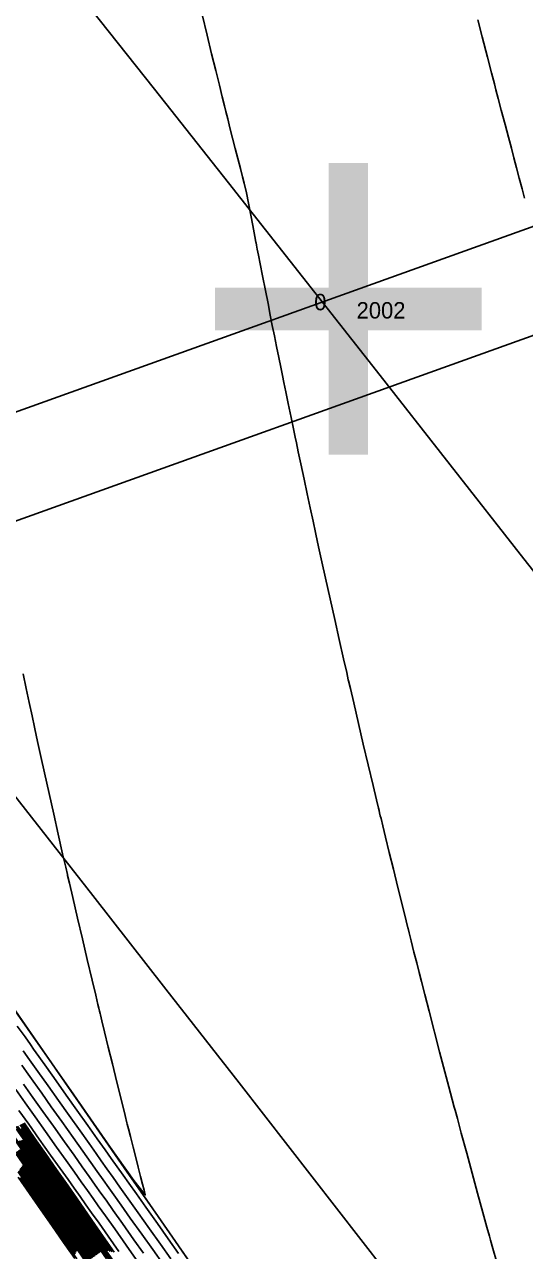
# Model space of a CAD drawing. Extents: x 74655 to 77873, y 48844 to 50507.
# Drawn here: x 75126.62 to 75130.27, y 49766.3 to 49775.27 of the extents above; entities that cross this region are included whole.
import ezdxf

# ---------------------------------------------------------------- set-up
doc = ezdxf.new("R2010")
doc.units = 0
for name, color, linetype in [('2', 7, 'Continuous'), ('24', 7, 'Continuous'), ('50', 7, 'Continuous'), ('62', 7, 'Continuous'), ('7', 7, 'Continuous')]:
    doc.layers.add(name, color=color, linetype=linetype)

msp = doc.modelspace()

# ---------------------------------------------------------------- linework, layer by layer
at = {"layer": '2'}
for radius in [833.5111, 829.5111, 818.5111, 807.5111, 803.5111]:
    msp.add_arc((74494.001, 49274.1292), radius, 30.8050451, 46.6978585, dxfattribs=at)
at = {"layer": '50'}
for points in [[(75127.9143, 49775.3434), (75127.9509, 49775.193), (75127.9843, 49775.0567), (75128.0143, 49774.9346), (75128.0411, 49774.8267), (75128.0624, 49774.7408), (75128.0783, 49774.6767), (75128.0888, 49774.6345), (75128.1023, 49774.5809), (75128.1186, 49774.5159), (75128.1379, 49774.4395), (75128.1569, 49774.3641), (75128.1757, 49774.2898), (75128.1943, 49774.2166), (75128.2096, 49774.1564), (75128.2217, 49774.1091), (75128.2394, 49774.0404)], [(75129.9314, 49775.3053), (75129.9632, 49775.1814), (75130.0016, 49775.0321), (75130.0311, 49774.9177), (75130.0517, 49774.838), (75130.0634, 49774.7931), (75130.0803, 49774.7285), (75130.1024, 49774.6442), (75130.1297, 49774.5403), (75130.1541, 49774.4474), (75130.1758, 49774.3655), (75130.1945, 49774.2947), (75130.214, 49774.2216), (75130.2341, 49774.1462), (75130.2549, 49774.0686), (75130.2731, 49774.0005)], [(75129.6515, 49767.7536), (75129.5743, 49768.0519), (75129.5429, 49768.1734), (75129.5187, 49768.2673), (75129.5018, 49768.3336), (75129.4836, 49768.4056), (75129.4639, 49768.4832), (75129.4429, 49768.5665), (75129.4284, 49768.624), (75129.4205, 49768.6556), (75129.419, 49768.6615), (75129.4061, 49768.7135), (75129.3818, 49768.8116), (75129.346, 49768.9558), (75129.313, 49769.0896), (75129.2828, 49769.2129), (75129.2554, 49769.3258), (75129.2353, 49769.4082), (75129.2227, 49769.4602), (75129.2175, 49769.4818), (75129.2128, 49769.5015), (75129.2084, 49769.5195), (75129.2046, 49769.5356), (75129.19, 49769.5967), (75129.1649, 49769.7027), (75129.129, 49769.8538), (75129.0934, 49770.005), (75129.058, 49770.1563), (75129.0229, 49770.3079), (75128.9988, 49770.4117), (75128.9858, 49770.4679), (75128.9838, 49770.4765), (75128.9717, 49770.53), (75128.9494, 49770.6285), (75128.9169, 49770.7719), (75128.884, 49770.9184), (75128.8506, 49771.0679), (75128.8169, 49771.2203), (75128.7903, 49771.3404), (75128.771, 49771.4282), (75128.759, 49771.4836), (75128.7439, 49771.553), (75128.7259, 49771.6365), (75128.7049, 49771.7341), (75128.683, 49771.8366), (75128.6601, 49771.944), (75128.6363, 49772.0563), (75128.6176, 49772.1449), (75128.6039, 49772.2098), (75128.5954, 49772.2509), (75128.5825, 49772.3126), (75128.5655, 49772.3949), (75128.5442, 49772.4977), (75128.5266, 49772.5833), (75128.5125, 49772.6517), (75128.5021, 49772.7027), (75128.4897, 49772.7636), (75128.4754, 49772.8345), (75128.4591, 49772.9152), (75128.4433, 49772.9936), (75128.4281, 49773.0696), (75128.4134, 49773.1432), (75128.3965, 49773.2284), (75128.3775, 49773.3251), (75128.3562, 49773.4332), (75128.3393, 49773.5196), (75128.3266, 49773.5843), (75128.3183, 49773.6273), (75128.3125, 49773.6572), (75128.3092, 49773.674), (75128.3085, 49773.6778), (75128.3004, 49773.7202), (75128.285, 49773.8012), (75128.2394, 49774.0404)], [(75122.5232, 49773.8581), (75123.1719, 49772.9229), (75123.5385, 49772.3944), (75123.9474, 49771.8049), (75124.3985, 49771.1544), (75124.8235, 49770.5418), (75125.2223, 49769.9668), (75125.5949, 49769.4296), (75126.0081, 49768.834), (75126.4618, 49768.1799), (75126.956, 49767.4673), (75127.313, 49766.9527), (75127.5327, 49766.636), (75127.6974, 49766.3984)], [(75126.6058, 49770.5193), (75126.6287, 49770.4119), (75126.6506, 49770.3094), (75126.6716, 49770.2118), (75126.6896, 49770.1283), (75126.7047, 49770.0589), (75126.7167, 49770.0035), (75126.736, 49769.9157), (75126.7626, 49769.7956), (75126.7963, 49769.6431), (75126.8297, 49769.4937), (75126.8626, 49769.3472), (75126.8951, 49769.2037), (75126.9174, 49769.1052), (75126.9295, 49769.0517), (75126.9315, 49769.0432), (75126.9445, 49768.987), (75126.9686, 49768.8831), (75127.0037, 49768.7316), (75127.0391, 49768.5803), (75127.0747, 49768.4291), (75127.1105, 49768.278), (75127.1366, 49768.1684), (75127.1529, 49768.1001), (75127.1593, 49768.0731), (75127.1645, 49768.0516), (75127.1684, 49768.0354), (75127.171, 49768.0247), (75127.1819, 49767.9799), (75127.201, 49767.9011), (75127.2285, 49767.7882), (75127.2587, 49767.6649), (75127.2917, 49767.5311), (75127.3275, 49767.3868), (75127.3521, 49767.2876), (75127.3655, 49767.2334), (75127.3679, 49767.2241), (75127.3761, 49767.1913), (75127.3903, 49767.135), (75127.4105, 49767.0551), (75127.4295, 49766.9798), (75127.4475, 49766.9089), (75127.4644, 49766.8426), (75127.4787, 49766.7867), (75127.4904, 49766.7414), (75127.4994, 49766.7065), (75127.4166, 49766.8113), (75127.242, 49767.0557), (75126.9756, 49767.4397), (75126.6607, 49767.8937), (75126.2974, 49768.4176)], [(75125.6878, 49769.2951), (75126.2036, 49768.5515), (75126.4853, 49768.1452), (75126.791, 49767.7046), (75127.1205, 49767.2296), (75127.3676, 49766.8733), (75127.5323, 49766.6357), (75127.6971, 49766.3982)], [(75127.7432, 49766.2785), (75127.6673, 49766.3856), (75127.5876, 49766.4982), (75127.504, 49766.6161), (75127.4345, 49766.7142), (75127.379, 49766.7925), (75127.3375, 49766.851), (75127.2947, 49766.9113), (75127.2506, 49766.9735), (75127.2052, 49767.0375), (75127.1482, 49767.118), (75127.0795, 49767.2148), (75126.9991, 49767.3281), (75126.9218, 49767.4371), (75126.8476, 49767.5417), (75126.7765, 49767.6419), (75126.7215, 49767.7194), (75126.6825, 49767.7743), (75126.6596, 49767.8066), (75126.6199, 49767.8625), (75126.5634, 49767.9421)], [(75127.6862, 49766.2389), (75127.6102, 49766.346), (75127.5305, 49766.4586), (75127.4469, 49766.5765), (75127.3747, 49766.6784), (75127.3138, 49766.7642), (75127.2644, 49766.834), (75127.2189, 49766.8981), (75127.1775, 49766.9565), (75127.1401, 49767.0092), (75127.0884, 49767.0821), (75127.0224, 49767.1752), (75126.942, 49767.2885), (75126.8639, 49767.3986), (75126.7881, 49767.5055), (75126.7145, 49767.6092), (75126.6538, 49767.6947), (75126.606, 49767.7621)], [(75129.6515, 49767.7536), (75129.7192, 49767.4972), (75129.7435, 49767.4049), (75129.7585, 49767.3485), (75129.7639, 49767.3281), (75129.7809, 49767.2651), (75129.8093, 49767.1595), (75129.8493, 49767.0114), (75129.8891, 49766.8649), (75129.9286, 49766.7203), (75129.968, 49766.5773), (75129.997, 49766.4721), (75130.0156, 49766.4048), (75130.0239, 49766.3751), (75130.0408, 49766.3146), (75130.0665, 49766.2232)], [(75126.5955, 49767.657), (75126.6303, 49767.6078), (75126.6791, 49767.5391), (75126.7418, 49767.4507), (75126.8115, 49767.3524), (75126.8882, 49767.2444), (75126.9718, 49767.1265), (75127.0431, 49767.026), (75127.1019, 49766.943), (75127.1484, 49766.8774), (75127.1918, 49766.8162), (75127.2321, 49766.7595), (75127.2691, 49766.7072), (75127.3217, 49766.633), (75127.3898, 49766.5369), (75127.4734, 49766.419), (75127.5532, 49766.3065), (75127.6291, 49766.1993)], [(75127.4331, 49766.2355), (75127.3592, 49766.3398), (75127.2757, 49766.4577), (75127.2076, 49766.5538), (75127.155, 49766.628), (75127.1179, 49766.6803), (75127.0766, 49766.7386), (75127.031, 49766.8028), (75126.9812, 49766.873), (75126.9213, 49766.9575), (75126.8511, 49767.0565), (75126.7708, 49767.1698), (75126.6941, 49767.2779), (75126.621, 49767.3809), (75126.5516, 49767.4787)], [(75127.4861, 49766.2809), (75127.4163, 49766.3794), (75127.3327, 49766.4973), (75127.2647, 49766.5934), (75127.2121, 49766.6676), (75127.175, 49766.7199), (75127.1336, 49766.7782), (75127.0881, 49766.8424), (75127.0383, 49766.9126), (75126.9784, 49766.9971), (75126.9082, 49767.0961), (75126.8278, 49767.2094), (75126.7511, 49767.3175), (75126.6781, 49767.4205), (75126.6087, 49767.5183)], [(75126.5757, 49767.3247), (75126.6469, 49767.2243), (75126.7241, 49767.1155), (75126.8071, 49766.9984), (75126.8773, 49766.8994), (75126.9347, 49766.8185), (75126.9792, 49766.7558), (75127.0228, 49766.6944), (75127.0654, 49766.6343), (75127.107, 49766.5755), (75127.1611, 49766.4992), (75127.2277, 49766.4052), (75127.3067, 49766.2938)], [(75127.239, 49766.2249), (75127.1349, 49766.3745), (75127.0247, 49766.5329), (75126.932, 49766.6661), (75126.8568, 49766.7742), (75126.7991, 49766.8571), (75126.7409, 49766.9408), (75126.6822, 49767.0251), (75126.623, 49767.1102), (75126.556, 49767.2065)], [(75127.2555, 49766.2197), (75127.1515, 49766.3691), (75127.0399, 49766.5295), (75126.9467, 49766.6634), (75126.8719, 49766.771), (75126.8154, 49766.8521), (75126.7571, 49766.9359), (75126.6968, 49767.0226), (75126.6346, 49767.1119), (75126.5657, 49767.211)], [(75127.2277, 49766.2965), (75127.1564, 49766.399), (75127.0766, 49766.5137), (75126.9881, 49766.6408), (75126.8912, 49766.7801), (75126.8038, 49766.9057), (75126.7261, 49767.0174), (75126.6579, 49767.1154), (75126.585, 49767.2202)], [(75127.2426, 49766.2936), (75127.1682, 49766.4005), (75127.0872, 49766.5168), (75126.9998, 49766.6425), (75126.9058, 49766.7776), (75126.8194, 49766.9017), (75126.7407, 49767.0149), (75126.6696, 49767.1171), (75126.5946, 49767.2248)], [(75127.2575, 49766.2906), (75127.1799, 49766.4021), (75127.0979, 49766.5199), (75127.0114, 49766.6442), (75126.9204, 49766.775), (75126.835, 49766.8977), (75126.7553, 49767.0123), (75126.6812, 49767.1188), (75126.6043, 49767.2293)], [(75127.2723, 49766.2877), (75127.1917, 49766.4036), (75127.1086, 49766.523), (75127.0231, 49766.646), (75126.935, 49766.7725), (75126.8507, 49766.8937), (75126.7699, 49767.0097), (75126.6928, 49767.1205), (75126.6139, 49767.2339)], [(75127.1357, 49766.2628), (75127.0165, 49766.4341), (75126.908, 49766.59), (75126.8101, 49766.7306), (75126.7229, 49766.8559), (75126.6235, 49766.9987), (75126.5119, 49767.1591)], [(75127.1443, 49766.2688), (75127.0251, 49766.4401), (75126.9176, 49766.5946), (75126.8218, 49766.7323), (75126.7376, 49766.8533), (75126.6392, 49766.9947), (75126.5265, 49767.1566)], [(75127.2156, 49766.2402), (75127.133, 49766.3588), (75127.0494, 49766.479), (75126.9647, 49766.6007), (75126.8789, 49766.724), (75126.7953, 49766.8442), (75126.7138, 49766.9612), (75126.6345, 49767.0753), (75126.5541, 49767.1908)], [(75126.5917, 49767.192), (75126.6637, 49767.0886), (75126.7462, 49766.97), (75126.8288, 49766.8514), (75126.9113, 49766.7327), (75126.9939, 49766.6141), (75127.0806, 49766.4896), (75127.1713, 49766.3591), (75127.2662, 49766.2228)], [(75127.1097, 49766.2448), (75126.9905, 49766.4161), (75126.8947, 49766.5538), (75126.8222, 49766.658), (75126.773, 49766.7286), (75126.7138, 49766.8137), (75126.6445, 49766.9132), (75126.5652, 49767.0272)], [(75127.1183, 49766.2508), (75126.9992, 49766.4221), (75126.9033, 49766.5598), (75126.8308, 49766.664), (75126.7817, 49766.7346), (75126.7225, 49766.8197), (75126.6532, 49766.9192), (75126.5739, 49767.0332)], [(75127.153, 49766.2748), (75127.0338, 49766.4461), (75126.9273, 49766.5992), (75126.8334, 49766.7341), (75126.7522, 49766.8508), (75126.6823, 49766.9512), (75126.6237, 49767.0354), (75126.5764, 49767.1033)], [(75127.127, 49766.2568), (75127.0078, 49766.4281), (75126.912, 49766.5658), (75126.8395, 49766.67), (75126.7903, 49766.7406), (75126.7311, 49766.8257), (75126.6619, 49766.9252), (75126.5825, 49767.0392)], [(75127.1616, 49766.2808), (75127.0424, 49766.4521), (75126.9369, 49766.6037), (75126.845, 49766.7358), (75126.7668, 49766.8482), (75126.6979, 49766.9472), (75126.6383, 49767.0328), (75126.5881, 49767.105)], [(75127.1703, 49766.2868), (75127.0511, 49766.4581), (75126.9466, 49766.6083), (75126.8567, 49766.7375), (75126.7814, 49766.8456), (75126.7135, 49766.9432), (75126.653, 49767.0303), (75126.5997, 49767.1068)], [(75126.5523, 49767.0088), (75126.6498, 49766.8687), (75126.7519, 49766.722), (75126.8597, 49766.5671), (75126.9732, 49766.4041), (75127.0924, 49766.2328)], [(75127.101, 49766.2388), (75126.9818, 49766.4101), (75126.886, 49766.5478), (75126.8135, 49766.652), (75126.7644, 49766.7226), (75126.7052, 49766.8077), (75126.6359, 49766.9072), (75126.5565, 49767.0212)], [(75126.9863, 49766.2745), (75126.9013, 49766.3966), (75126.818, 49766.5164), (75126.7363, 49766.6338), (75126.6532, 49766.7532), (75126.5687, 49766.8747)], [(75126.9922, 49766.2845), (75126.9068, 49766.4073), (75126.8239, 49766.5264), (75126.7436, 49766.6418), (75126.6606, 49766.761), (75126.575, 49766.884)], [(75126.9981, 49766.2944), (75126.9122, 49766.4179), (75126.8298, 49766.5363), (75126.7509, 49766.6497), (75126.6681, 49766.7688), (75126.5813, 49766.8933)], [(75127.0948, 49766.1739), (75127.0041, 49766.3043), (75126.9177, 49766.4285), (75126.8357, 49766.5463), (75126.7582, 49766.6577), (75126.6755, 49766.7765), (75126.5877, 49766.9027)], [(75127.1021, 49766.1819), (75127.01, 49766.3143), (75126.9231, 49766.4391), (75126.8416, 49766.5562), (75126.7654, 49766.6657), (75126.6829, 49766.7843), (75126.594, 49766.912)], [(75127.1094, 49766.1899), (75127.0159, 49766.3242), (75126.9286, 49766.4497), (75126.8475, 49766.5662), (75126.7727, 49766.6737), (75126.6903, 49766.7921), (75126.6004, 49766.9214)], [(75126.5701, 49766.8357), (75126.6525, 49766.7173), (75126.7358, 49766.5977), (75126.8198, 49766.4769), (75126.9023, 49766.3584), (75126.9833, 49766.2419)], [(75126.5852, 49766.8325), (75126.6672, 49766.7146), (75126.751, 49766.5943), (75126.8364, 49766.4715), (75126.9188, 49766.3531), (75126.9982, 49766.239)], [(75128.1404, 49765.7591), (75127.6971, 49766.3982)], [(75128.4814, 49765.2681), (75127.6974, 49766.3984)]]:
    msp.add_lwpolyline(points, dxfattribs=at)
at = {"layer": '7'}
for p, q in [((74963.6526, 49713.9728), (75340.1411, 49849.089)), ((74963.9059, 49713.2669), (75340.3944, 49848.3831))]:
    msp.add_line(p, q, dxfattribs=at)

# ---------------------------------------------------------------- texts
at = {"layer": '24'}
msp.add_text('+', height=3, dxfattribs=at).set_placement((75127.8142, 49771.7398))
at = {"layer": '62'}
for s, p in [('0', (75128.7346, 49773.1798)), ('2002', (75129.0446, 49773.1198))]:
    msp.add_text(s, height=0.12, dxfattribs=at).set_placement(p)

doc.saveas('drawing.dxf')
